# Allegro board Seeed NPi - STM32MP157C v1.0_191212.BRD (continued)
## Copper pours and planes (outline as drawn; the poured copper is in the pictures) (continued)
N3991771 on LYR3: 35.21,55.09 31.28,55.09 28.48,52.3 28.48,50.9 28.86,50.52 32.8,50.52 35.47,53.18 35.47,54.84
N4540513 on BOTTOM: 33.18,24.1 31.66,24.1 31.28,23.72 30.26,23.72 30.13,23.85 30.13,24.74 30.26,24.86 33.18,24.86 33.43,24.61 33.43,24.36
N4540517 on BOTTOM: 29.24,23.85 28.74,23.85 28.48,24.1 28.48,25.88 28.61,26.01 29.24,26.01 29.5,25.75 29.5,24.1
N4540827 on BOTTOM: 36.23,32.1 35.59,31.47 35.59,27.66 35.85,27.4 38.51,27.4 38.77,27.66 38.77,29.05 39.15,29.44 46.9,29.44 47.79,30.32 47.79,33.88 47.53,34.13 45.37,34.13 45.25,34.01 45.25,32.36 44.99,32.1
N4563547 on BOTTOM: 37.5,38.07 36.86,38.07 35.85,39.09 34.2,39.09 33.69,38.58 33.69,36.93 34.2,36.42 37.5,36.42 37.75,36.67 37.75,37.82
N4563559 on BOTTOM: 39.91,36.04 38.64,36.04 38.39,36.29 38.39,39.85 38.77,40.23 39.91,40.23 40.17,39.98 40.17,36.29

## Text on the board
Ref Des/Silkscreen Bottom: J22 | GND | RST | SCLK | SDIO | J21 | U6 | 1 | 39 | 2 | 40 | DVP_Camera | SD | Seeed NPi-STM32MP157C
Ref Des/Silkscreen Top: PWR | RST | J2 | J5 | USER | J11 | ANT1 | 39 | 1 | J20 | RXD | GND | 40 | 2 | J8 | 69 | J13 | J17 | CON1 | EMMC | J9 | J14 | BOOT | USER0 | SD_CARD | USER1 | USER2 | 70 | J10 | U3 | J7 | ANT2 | (OZ) | USB | Digital | I2C | Audio | DSI | ETH | DC IN 12V | LAYER 1 - PRIMARY SIDE - SIGNAL | LAYER 2 - GROUND PLANE | LAYER 3 - SIGNAL | LAYER 4 - SIGNAL | LAYER 5 - SPLIT POWER PLANE | LAYER 6 - SECONDARY SIDE - SIGNAL | LAYER# | COPPER WEIGHT | HALF+PLATING | IMPEDANCE CONTROL | +/- 10% | 50ohm SINGLE ENDED | TRACE WIDTH | TRACE WIDTH / SPACE | 90ohm DIFFERENTIAL | 100ohm DIFFERENTIAL | - | + | 4.75&15 | 4.75 | 4.5/6.5 | 5.0/7.0 | 3.75/7.25 | 4.00/8.00 | LAYER STACK-UP - ALL DIMENSIONS IN INCHES
User.20: 1 | 2
User.22: 2 | 70 | 69 | 1
User.24: 69 | 1 | 2 | 70 | R | N | L | J | G | E | C | A | 9 | 7 | 3
User.25: 70 | 2 | 69 | 1 | R | N | L | J | G | E | C | A | 9 | 7 | 3
User.32: FIGURE | FINISHED_SIZE | 51.18x19.69 | 59.06x39.37 | 59.06x47.24 | 110.24x31.5 | ROTATION | 0.000 | 90.000 | SLOT HOLES: TOP to BOTTOM | ALL UNITS ARE IN MILS | TOLERANCE_DRILL | +0.0/-0.0 | PLATED | QTY | 4 | 1 | 2 | 12 | TOTAL HOLES:
User.33: FIGURE | FINISHED_SIZE | 8.0 | 35.0 | 35.43 | 36.0 | 41.34 | 66.93 | 78.74 | 92.0 | 110.24 | 23.62 | 51.18 | 127.95 | ROTATION | - | DRILL CHART: TOP to BOTTOM | ALL UNITS ARE IN MILS | TOLERANCE_DRILL | +0.0/-0.0 | +3.0/-3.0 | PLATED | NON-PLATED | QTY | 874 | 43 | 10 | 8 | 4 | 2 | 3 | 959 | TOTAL HOLES:
